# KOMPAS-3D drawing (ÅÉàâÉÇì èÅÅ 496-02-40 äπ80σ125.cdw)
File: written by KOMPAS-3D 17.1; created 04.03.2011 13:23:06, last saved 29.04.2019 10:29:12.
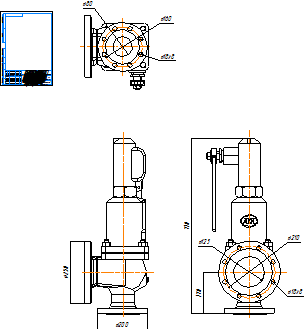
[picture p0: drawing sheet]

Sheet 1: A4, portrait

Title block, sheet 1: name: ПРЕГРАН КПП 496-02-40 / Ду80х125; material: Внимание! Данный продукт является объектом авторского права ООО «Торговый Дом АДЛ». / Запрещается изменение, копирование, распространение / (в том числе путем копирования на другие сайты и ресурсы в Интернете) / или любое иное использование информации и объектов без предварительного / согласия правообладателя (ООО «Торговый Дом АДЛ»).; scale: 1:1; sheets: 1; organisation: ООО "Торговый дом АДЛ"; sheet format: A4; stored path: C:\Users\tra\Desktop\2д чертежи\Предохранительные клапаны ПРЕГРАН\ПРЕГРАН 496\ПРЕГРАН КПП 496-02-40\KOMPAS 2D\ПРЕГРАН КПП 496-02-40 Ду80х125.cdw

Views: Спереди 1, Проекционный вид 2, Проекционный вид 3
Dimensions and other numbers on the sheet: 200; 250; 170; 710; 210; 18; 125; 160; 80; 1:1; 1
